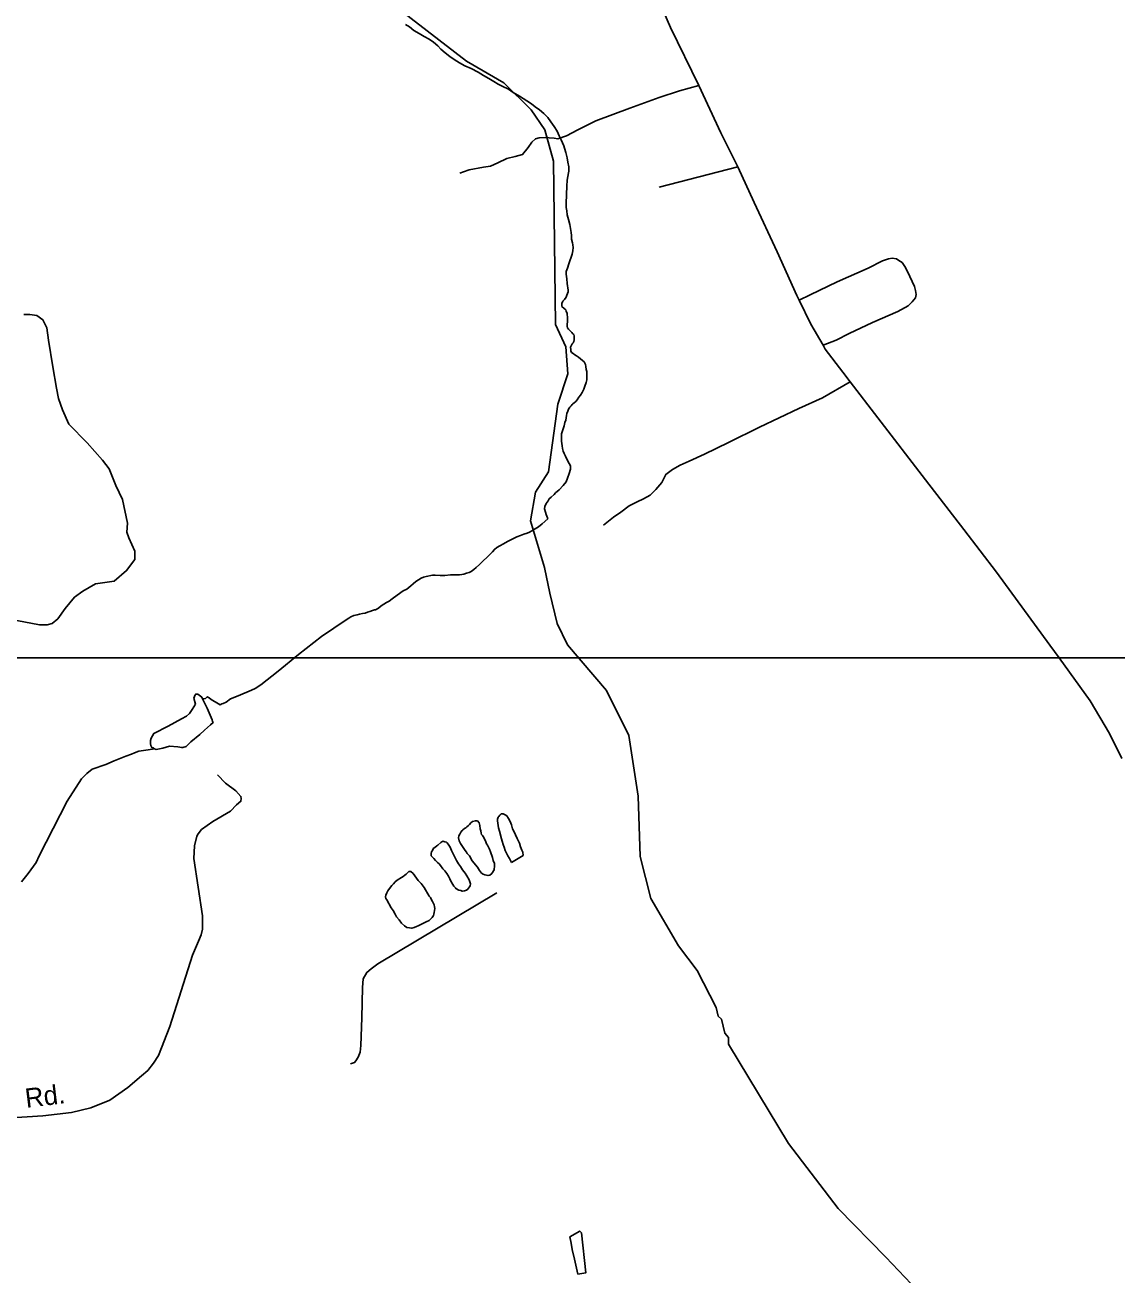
# Model space of a CAD drawing. Extents: x 2206922 to 2357709, y 510027 to 673830.
# Drawn here: x 2296847 to 2302239, y 564008 to 570183 of the extents above; entities that cross this region are included whole.
import ezdxf

# ---------------------------------------------------------------- set-up
doc = ezdxf.new("R2010")
doc.units = 0
for name, color, linetype in [('Exist Hydrographic Creek Single Shore', 7, 'Continuous'), ('Exist Hydrographic Misc Water Feature', 7, 'Continuous'), ('Exist Road Non-System Type 51', 7, 'Continuous'), ('Exist Road Non-System Type 51 Label', 7, 'Continuous'), ('Exist Road Secondary Type 51 Attributed', 7, 'Continuous'), ('Map Preparation Inset Cut Line', 7, 'Continuous')]:
    doc.layers.add(name, color=color, linetype=linetype)

msp = doc.modelspace()

# ---------------------------------------------------------------- linework, layer by layer
at = {"layer": 'Exist Hydrographic Creek Single Shore'}
msp.add_lwpolyline([(2301317.2, 563865.6), (2301098.2, 564096.3), (2300862.2, 564336.2), (2300617.1, 564657.7), (2300320, 565147.7), (2300320, 565180.5), (2300303, 565202.9), (2300286, 565271.1), (2300269.1, 565286.8), (2300260.1, 565329.1), (2300166, 565512.4), (2300074.1, 565633.3), (2299938, 565867.4), (2299885.1, 566075.2), (2299874, 566373.4), (2299829.1, 566673.5), (2299719, 566895.4), (2299525, 567120.6), (2299474, 567226.9), (2299439.1, 567376.4), (2299412, 567503.3), (2299343.1, 567733.5), (2299367.1, 567875.5), (2299432.1, 567976.6), (2299478.1, 568309.9), (2299527.1, 568459.5), (2299517, 568593.7), (2299466, 568703.2), (2299456.9, 569510.1), (2299414.1, 569665.8), (2299346, 569764.8), (2299211.1, 569897.2), (2299026.9, 570004.7), (2298696.6, 570260.6)], dxfattribs=at)
at = {"layer": 'Exist Hydrographic Misc Water Feature'}
for points in [[(2299510.7, 568827.2), (2299518.7, 568839.4), (2299522.5, 568849.3), (2299528.5, 568865.5), (2299528.3, 568873.6), (2299524.2, 568905.5), (2299521.7, 568929.4), (2299519.3, 568953.2), (2299519.7, 568965.3), (2299525.4, 568981.5), (2299532.8, 569003.5), (2299548.6, 569051.8), (2299552.5, 569067.5), (2299554.3, 569083.8), (2299551.9, 569097.6), (2299549.8, 569107.6), (2299545.9, 569125.6), (2299545.5, 569143.5), (2299543.3, 569157.7), (2299541, 569177.5), (2299536.7, 569197.6), (2299530.8, 569223.2), (2299524.2, 569245.3), (2299522.3, 569265.4), (2299519.9, 569281.2), (2299519.5, 569301.1), (2299522.5, 569389.1), (2299524.4, 569415.2), (2299526.4, 569427), (2299532.2, 569461.4), (2299532, 569483.4), (2299527.5, 569505.1), (2299523.6, 569527.2), (2299517.2, 569552.9), (2299511.1, 569574.9), (2299506.8, 569586.9), (2299494.3, 569616.8), (2299484.4, 569636.5), (2299474, 569658.4), (2299459.6, 569682.4), (2299443.8, 569704.3), (2299429, 569725.9), (2299409, 569745.6), (2299386.8, 569763.5), (2299366.5, 569779.1), (2299348.5, 569793.2), (2299324.3, 569809), (2299288.2, 569832.3), (2299258, 569850.2), (2299233.8, 569865.6), (2299203.7, 569881.5), (2299183.8, 569891.4), (2299161.5, 569904.9), (2299137.3, 569918.7), (2299111, 569934.4), (2299085.2, 569950.1), (2299050.7, 569967.8), (2299018.5, 569981.6), (2298992.7, 569997.3), (2298966.4, 570013), (2298944.3, 570028.4), (2298921.7, 570046.4), (2298900, 570063.9), (2298885.7, 570079.9), (2298863.7, 570097.8), (2298843.2, 570113.4), (2298817.2, 570127.1), (2298793, 570140.9), (2298766.7, 570156.6), (2298744.6, 570174.5), (2298724.9, 570186)], [(2299428.4, 567743.1), (2299426.4, 567749), (2299420.2, 567765), (2299416.3, 567776.9), (2299412, 567793), (2299414.1, 567804.9), (2299419.8, 567819), (2299429.5, 567832.9), (2299435.8, 567842.9), (2299445.7, 567851.2), (2299459.2, 567863.3), (2299467.2, 567871.4), (2299485.2, 567887.4), (2299504.7, 567907.9), (2299518.4, 567926.2), (2299526, 567944.1), (2299533.8, 567968.1), (2299539.8, 567988.3), (2299540, 568004.1), (2299537.3, 568012.1), (2299531.4, 568022), (2299527.7, 568029.8), (2299521.1, 568041.7), (2299515.4, 568053.9), (2299509, 568065.9), (2299504.9, 568077.8), (2299501, 568091.8), (2299498.6, 568103.5), (2299496.7, 568127.8), (2299496.3, 568147.7), (2299495.9, 568163.5), (2299501.8, 568183.7), (2299508, 568197.8), (2299509.8, 568203.6), (2299513.3, 568219.7), (2299517, 568231.8), (2299519.1, 568242), (2299521.1, 568253.9), (2299522.8, 568263.8), (2299526.9, 568275.7), (2299530.8, 568286.1), (2299536.5, 568295.7), (2299544.5, 568302.3), (2299548.4, 568308.1), (2299552.5, 568312), (2299558.2, 568316), (2299566.4, 568324.1), (2299574, 568332.2), (2299582, 568344.4), (2299590.2, 568354.5), (2299598, 568368.4), (2299605.8, 568384.6), (2299611.5, 568398.8), (2299617.1, 568416.6), (2299621.2, 568430.6), (2299621, 568444.8), (2299620.8, 568456.6), (2299621, 568470.8), (2299618.3, 568480.9), (2299616.3, 568496.6), (2299614.2, 568506.6), (2299608.1, 568518.5), (2299600.1, 568526.6), (2299589.8, 568534.2), (2299580.2, 568542.2), (2299569.7, 568548.2), (2299561.7, 568553.9), (2299553.7, 568560), (2299545.9, 568566), (2299541.6, 568574), (2299541.8, 568580), (2299541.2, 568591.8), (2299543.1, 568598), (2299545.5, 568601.8), (2299549, 568608.1), (2299553.5, 568613.9), (2299557, 568619.9), (2299559.3, 568628.1), (2299558.6, 568637.9), (2299558.6, 568648), (2299556.6, 568654), (2299552.7, 568657.9), (2299546.5, 568664.1), (2299536.5, 568673.7), (2299530.8, 568681.5), (2299526.2, 568687.8), (2299524.2, 568693.8), (2299524.4, 568699.4), (2299524, 568705.5), (2299526, 568717.4), (2299526.2, 568723.5), (2299525.6, 568735.7), (2299523.8, 568757.5), (2299519.5, 568769.5), (2299517.8, 568775.4), (2299509.4, 568783.2), (2299497.3, 568793.1), (2299497.1, 568807.3), (2299503.1, 568819.4), (2299510.7, 568827.2)], [(2298432.5, 567244.6), (2298446.6, 567253), (2298456.1, 567258.9), (2298470.4, 567265.3), (2298486.4, 567269.4), (2298498.5, 567273.2), (2298512.5, 567275.6), (2298526, 567277.6), (2298538.1, 567281.8), (2298549.8, 567285.7), (2298562.1, 567290), (2298572.1, 567294.2), (2298578.1, 567294.1), (2298591.6, 567302.1), (2298605.8, 567314.6), (2298619.3, 567322.7), (2298631.8, 567330.6), (2298645.5, 567337), (2298659.5, 567349.1), (2298684.9, 567367.2), (2298714.8, 567387.8), (2298732.7, 567395.7), (2298742.5, 567403.9), (2298752.4, 567412.2), (2298764.3, 567422.1), (2298776.4, 567434.1), (2298790.1, 567442.6), (2298802.2, 567450.5), (2298814.3, 567454.8), (2298828.2, 567458.8), (2298858.2, 567465.2), (2298871.7, 567465.2), (2298896.1, 567463.5), (2298910.3, 567463.9), (2298919.5, 567463.6), (2298948, 567466.3), (2298961.5, 567466.2), (2298991.9, 567466.6), (2299003.8, 567468.8), (2299013.8, 567470.9), (2299027.6, 567474.9), (2299039.9, 567479.2), (2299049.3, 567483), (2299063.4, 567493.5), (2299075.3, 567503.4), (2299091.3, 567517.7), (2299101, 567527.6), (2299111.2, 567537.8), (2299126.8, 567552.1), (2299140.5, 567566.2), (2299154.5, 567580.3), (2299164.5, 567592.2), (2299176.4, 567602.6), (2299192.2, 567610.8), (2299210.1, 567620.6), (2299229.9, 567631), (2299251.7, 567643.2), (2299275.3, 567655.4), (2299293.3, 567661.6), (2299309.7, 567667.7), (2299325.7, 567672.1), (2299337.4, 567678.1), (2299349.5, 567684.4), (2299363, 567692.5), (2299377.2, 567700.5), (2299391.1, 567710.5), (2299400.5, 567718.9), (2299428.4, 567743.1)], [(2297726.1, 566848.1), (2297727.9, 566854.3), (2297738, 566856.5), (2297746.2, 566864.6), (2297756.2, 566858.6), (2297765.9, 566850.6), (2297802.4, 566829), (2297810.2, 566825), (2297818, 566829), (2297825.9, 566831.1), (2297840.3, 566837.4), (2297862, 566853.6), (2297899.6, 566869.9), (2297965.6, 566896.4), (2297983.6, 566904.7), (2298011.3, 566922.8), (2298096.2, 566991.5), (2298197.7, 567072.7), (2298311.1, 567161.5), (2298371, 567204), (2298432.5, 567244.6)], [(2297726.1, 566848.1), (2297719.7, 566862.1), (2297700, 566878), (2297689.8, 566878), (2297687.7, 566873.8), (2297680, 566857.9), (2297688.2, 566827.9), (2297672.4, 566801.9), (2297658.8, 566781.6), (2297644.9, 566769.5), (2297619.1, 566755.1), (2297553.6, 566718.8), (2297483.5, 566683.9), (2297476.1, 566672.1), (2297469.8, 566660), (2297466.1, 566648), (2297466.5, 566631.8), (2297468.5, 566623.8), (2297472.4, 566613.9), (2297480.6, 566612.2), (2297486.8, 566608)], [(2297486.8, 566608), (2297494.6, 566604.4), (2297526.6, 566610.5), (2297560.2, 566620.9), (2297602, 566617), (2297620.3, 566613.5), (2297626.2, 566613.4), (2297642, 566619.5), (2297666.2, 566641.8), (2297709.7, 566678.3), (2297733.3, 566700.2), (2297763.2, 566726.6), (2297775.1, 566736.9), (2297773, 566742.9), (2297771, 566750.9), (2297746.6, 566808.6), (2297726.1, 566848.1)], [(2296829, 565950.4), (2296862.8, 565990.7), (2296902.2, 566045.2), (2296915.9, 566079.2), (2297055, 566348.2), (2297126.1, 566458.8), (2297151.7, 566484.9), (2297178, 566507.3), (2297245.4, 566530), (2297287.3, 566548.4), (2297344.9, 566571), (2297373, 566580.9), (2297386.7, 566587.4), (2297408.5, 566595.5), (2297454.6, 566601.9), (2297486.8, 566608)], [(2299040.9, 566078), (2299055, 566053.9), (2299081.3, 566022.4), (2299091.3, 566006.7), (2299095.4, 566000.4), (2299101.4, 565992.6), (2299109.6, 565988.6), (2299118, 565984.9), (2299125.8, 565982.9), (2299133.8, 565980.9), (2299141.8, 565982.9), (2299151.8, 565991.1), (2299163.3, 566009.3), (2299165.3, 566029.2), (2299164.7, 566041.5), (2299159, 566055.3), (2299154.9, 566070.9), (2299144.6, 566098.9), (2299140.1, 566110.9), (2299129.9, 566130.7), (2299126.2, 566138.5), (2299120, 566152.9), (2299115.7, 566160.8), (2299112, 566168.6), (2299105.5, 566178.5), (2299101.4, 566184.4), (2299099.5, 566190.4), (2299097.3, 566202.5), (2299095, 566212.6), (2299093, 566228.3), (2299089.1, 566242.3), (2299080.9, 566252), (2299070.6, 566252.3), (2299056.7, 566247.9), (2299048.9, 566241.8), (2299041.3, 566233.6), (2299035.1, 566227.6), (2299029, 566221.7), (2299023.2, 566217.7), (2299017.5, 566213.7), (2299009.3, 566207.7), (2299005.2, 566203.4), (2298999.5, 566195.3), (2298993.7, 566185.3), (2298989.8, 566177.3), (2298987.6, 566167.1), (2298990, 566153.4), (2298997.8, 566139.2), (2299004.4, 566129.3), (2299020.8, 566105.7), (2299026.5, 566097.5), (2299030.4, 566089.7), (2299040.9, 566078)], [(2299248.8, 566046.2), (2299238.6, 566066.1), (2299230.4, 566077.9), (2299224.6, 566092.1), (2299218.5, 566105.6), (2299212.1, 566121.5), (2299208, 566135.5), (2299203.5, 566151.6), (2299200, 566163.5), (2299189.3, 566201.2), (2299185, 566217.2), (2299182.8, 566229.3), (2299181.1, 566239.3), (2299180.5, 566251.2), (2299180.7, 566259.3), (2299182.8, 566269.1), (2299186.5, 566273.4), (2299190.8, 566279.3), (2299198.6, 566285.4), (2299202.5, 566285.6), (2299208.4, 566285.5), (2299218.3, 566281.6), (2299226.2, 566275.9), (2299234.5, 566263.7), (2299242.9, 566247.9), (2299249.2, 566232), (2299254.8, 566212), (2299261.3, 566200.1), (2299277.5, 566164.4), (2299288, 566140.5), (2299294.3, 566122.6), (2299300.1, 566106.7), (2299304.4, 566096.7), (2299306.4, 566081), (2299248.8, 566046.2)], [(2298919.3, 566004.7), (2298929.7, 565990.9), (2298937.5, 565978.8), (2298944.1, 565964.8), (2298948, 565956.9), (2298952.1, 565949), (2298954.6, 565945), (2298964.2, 565929.3), (2298972.6, 565921.2), (2298974.4, 565917.2), (2298988.6, 565909.5), (2298998.4, 565907.6), (2299006.2, 565903.6), (2299016.3, 565905.7), (2299026.3, 565909.8), (2299032.7, 565913.8), (2299044.2, 565929.9), (2299046.4, 565940.1), (2299039.9, 565960.1), (2299027.8, 565979.8), (2299019.6, 565993.6), (2299007.3, 566009.6), (2298997.2, 566025.4), (2298987.2, 566039.4), (2298977.1, 566055.1), (2298960.5, 566088.8), (2298952.7, 566105), (2298946.4, 566121), (2298940.4, 566130.8), (2298932.2, 566142.6), (2298928.1, 566146.4), (2298919.9, 566148.5), (2298910.1, 566150.4), (2298900, 566144.2), (2298886.1, 566132.1), (2298880.3, 566128.1), (2298870.1, 566119.9), (2298864.3, 566115.9), (2298858.4, 566105.8), (2298854.5, 566097.9), (2298852.8, 566089.7), (2298852.8, 566077.9), (2298864.9, 566066), (2298873.1, 566056.2), (2298883, 566046.2), (2298891.4, 566038.4), (2298899, 566030.4), (2298909.4, 566014.6), (2298919.3, 566004.7)], [(2298843, 565879.9), (2298848.7, 565872.1), (2298853.1, 565864.1), (2298859, 565853.9), (2298863.3, 565844), (2298867.4, 565836), (2298869.3, 565826.1), (2298869.7, 565818.3), (2298868, 565798.3), (2298865.8, 565790.1), (2298863.9, 565784.3), (2298858, 565774.2), (2298842, 565760), (2298828.4, 565751.9), (2298798.3, 565737.4), (2298788.3, 565733.2), (2298780.5, 565729.5), (2298768.8, 565725.2), (2298756.5, 565721), (2298745, 565723.1), (2298732.5, 565725), (2298720.6, 565732.9), (2298706.4, 565746.3), (2298694.1, 565762.4), (2298681.8, 565778), (2298674, 565790.1), (2298664, 565807.9), (2298655.6, 565822.1), (2298633.2, 565861.6), (2298629.1, 565867.5), (2298627.1, 565875.5), (2298628.9, 565883.7), (2298633, 565895.7), (2298639, 565905.7), (2298647, 565917.9), (2298658.7, 565932), (2298666.3, 565940.1), (2298674.2, 565949.9), (2298684.3, 565958.1), (2298706, 565972.3), (2298714, 565976.4), (2298721.8, 565982.5), (2298729.6, 565988.6), (2298735.8, 565994.6), (2298741.9, 566000.5), (2298751.8, 566000.7), (2298763.7, 565991.2), (2298788.3, 565957.1), (2298802.2, 565941.6), (2298818.4, 565921.7), (2298843, 565879.9)], [(2299576.5, 564012.7), (2299559.9, 564086.6), (2299549, 564134.5), (2299543.1, 564164.6), (2299536.9, 564196.3), (2299586.3, 564225), (2299594.3, 564216.9), (2299616.7, 564019.2), (2299576.5, 564012.7)]]:
    msp.add_lwpolyline(points, dxfattribs=at)
at = {"layer": 'Exist Road Non-System Type 51'}
msp.add_line((2300366.8, 569482.2), (2299978.5, 569382.1), dxfattribs=at)
for points in [[(2300174, 569885.1), (2300078.5, 569857.7), (2299977.8, 569825.3), (2299832.8, 569772.4), (2299665.6, 569709.2), (2299576.9, 569664.9), (2299520.6, 569635.8), (2299478, 569620.5), (2299459.2, 569623.9), (2299435.3, 569625.6), (2299414.9, 569627.3), (2299385.9, 569625.6), (2299367.1, 569620.5), (2299350, 569605.1), (2299331.3, 569577.8), (2299304, 569543.7), (2299266.4, 569533.4), (2299225.5, 569523.2), (2299181.1, 569502.7), (2299145.3, 569485.6), (2299111.2, 569480.5), (2299039.5, 569468.6), (2299012.2, 569458.3), (2298993.5, 569451.5)], [(2300669.5, 568824.5), (2300723.4, 568850.6), (2300858.2, 568913.8), (2301010, 568982.1), (2301081.6, 569017.9), (2301110.6, 569028.2), (2301129.4, 569031.6), (2301149.9, 569028.2), (2301161.8, 569019.6), (2301178.9, 569009.4), (2301194.2, 568985.5), (2301216.4, 568941.1), (2301238.6, 568891.6), (2301243.7, 568871.1), (2301247.1, 568852.3), (2301243.7, 568835.3), (2301228.4, 568816.5), (2301207.9, 568796), (2301156.7, 568768.7), (2301032.2, 568714.1), (2300916.2, 568659.4), (2300853, 568627), (2300787.6, 568601.2)], [(2296805.7, 567240.9), (2296917.4, 567220.4), (2296956.1, 567220.4), (2296981.2, 567227.2), (2297008.5, 567250), (2297044.9, 567301.3), (2297090.5, 567356), (2297131.5, 567385.6), (2297195.3, 567422.1), (2297286.4, 567435.8), (2297347.9, 567488.2), (2297388.9, 567542.9), (2297388.9, 567583.9), (2297359.3, 567650), (2297350.2, 567677.4), (2297352.5, 567723), (2297327.4, 567839.2), (2297295.5, 567907.6), (2297261.4, 567990.8), (2297229.5, 568034.1), (2297154.3, 568118.4), (2297063.2, 568211.9), (2297031.3, 568282.6), (2297012.7, 568338.6), (2297002.3, 568388.4), (2296983.2, 568494.1), (2296962.1, 568625.9), (2296953.6, 568687.8), (2296935.2, 568727.6), (2296905, 568747.4), (2296870.9, 568753.1), (2296840.9, 568752.7)], [(2300922.3, 568420.1), (2300784.8, 568341.9), (2300668.8, 568289), (2300474.3, 568196.9), (2300320.8, 568120), (2300203, 568063.7), (2300126.3, 568027.9), (2300081.9, 568009.1), (2300044.4, 567986.9), (2300012, 567963), (2300001.7, 567942.5), (2299991.5, 567923.7), (2299962.5, 567887.9), (2299933.5, 567860.6), (2299901.1, 567841.8), (2299870.4, 567828.1), (2299829.4, 567807.7), (2299788.5, 567776.9), (2299752.7, 567751.3), (2299703.2, 567712.1)], [(2296674.4, 564777.4), (2296934.2, 564793.7), (2297075.9, 564811), (2297171.5, 564833.9), (2297265.3, 564870.8), (2297354.7, 564933.6), (2297422, 564992.2), (2297453.8, 565018.5), (2297481.3, 565054.7), (2297505.1, 565092.9), (2297561.7, 565235.5), (2297674.2, 565588.2), (2297703.6, 565656.4), (2297717.2, 565688.5), (2297723, 565716.6), (2297722.3, 565782.6), (2297679.9, 566066.1), (2297683.1, 566128.1), (2297694.7, 566176.2), (2297702.5, 566188.2), (2297718.3, 566208.3), (2297773.9, 566248.8), (2297861.5, 566299.6), (2297891.1, 566330), (2297913.1, 566348.1), (2297914.7, 566362.1), (2297912.8, 566372.1), (2297888.5, 566399.8), (2297836.1, 566437.2), (2297797.8, 566479)], [(2299176.5, 565895.3), (2298588.5, 565545.1), (2298556.7, 565520.8), (2298535, 565502.5), (2298517.3, 565470.4), (2298513.8, 565428.4), (2298509.5, 565278.4), (2298505, 565142.4), (2298501.3, 565108.4), (2298491.5, 565084.2), (2298479.6, 565066.2), (2298473.8, 565058.1), (2298453.8, 565051.9)]]:
    msp.add_lwpolyline(points, dxfattribs=at)
at = {"layer": 'Exist Road Secondary Type 51 Attributed'}
msp.add_lwpolyline([(2302263.9, 566559.9), (2302202.5, 566682.8), (2302106.6, 566844.2), (2301953, 567057.4), (2301907.9, 567120), (2301644.6, 567479.9), (2301482.6, 567691.6), (2301293.2, 567935.7), (2301057.8, 568242.9), (2300922.3, 568420.1), (2300885.5, 568468.3), (2300798.4, 568582.6), (2300787.6, 568601.2), (2300726.8, 568705.5), (2300669.5, 568824.5), (2300658.6, 568847.2), (2300561.3, 569062.3), (2300447, 569306.4), (2300366.8, 569482.2), (2300283.2, 569651.2), (2300174, 569885.1), (2300033.6, 570170.5), (2299956.5, 570350.5)], dxfattribs=at)
at = {"layer": 'Map Preparation Inset Cut Line'}
for p, q in [((2301953, 567057.4), (2296290.5, 567057.4)), ((2305851.6, 567057.4), (2301953, 567057.4))]:
    msp.add_line(p, q, dxfattribs=at)

# ---------------------------------------------------------------- texts
at = {"layer": 'Exist Road Non-System Type 51 Label'}
msp.add_text('Rd.', height=95, rotation=6.96071, dxfattribs=at).set_placement((2296852.7, 564833.3))

doc.saveas('drawing.dxf')
